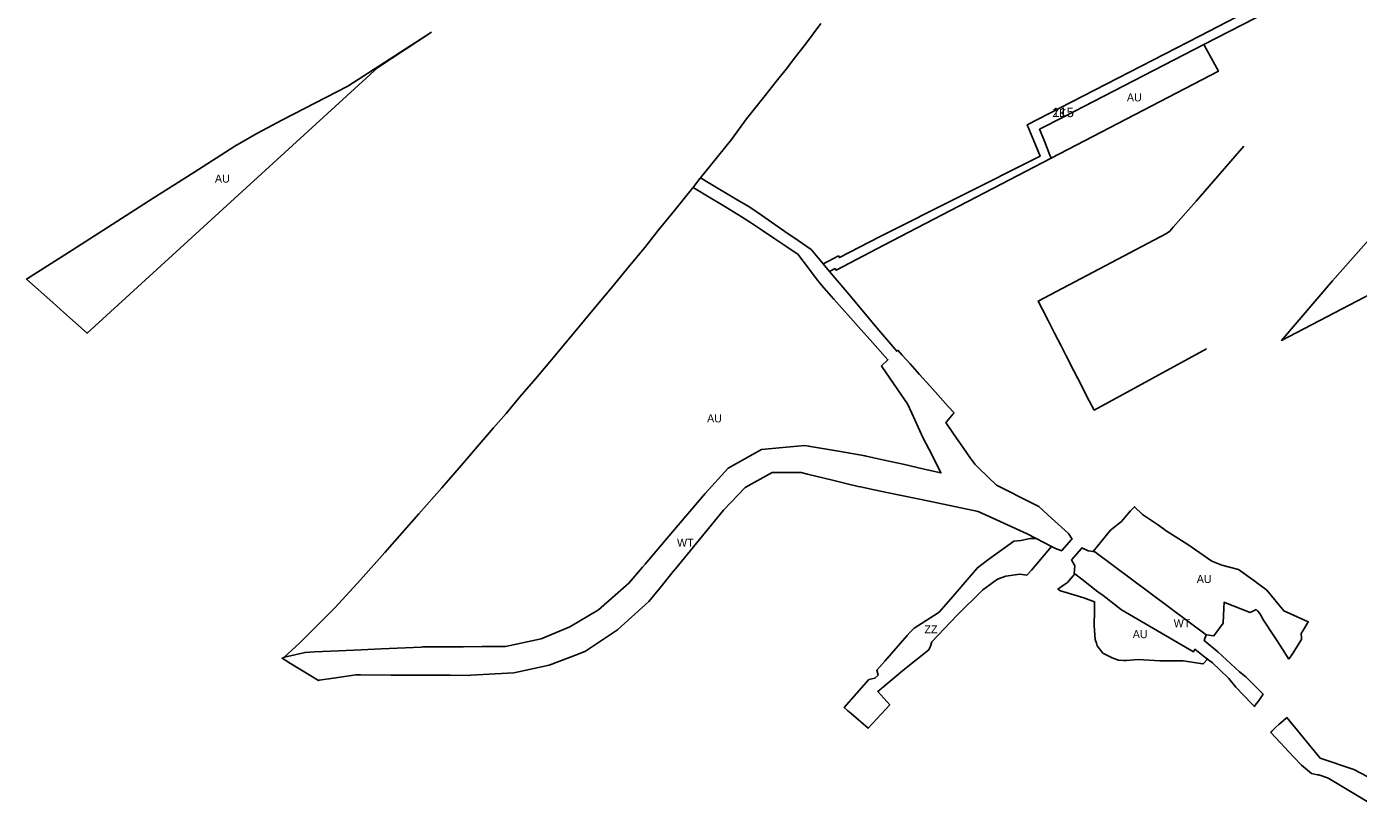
# Model space of a CAD drawing. Extents: x -537068 to -534056, y -1176840 to -1172401.
# Drawn here: x -536912 to -536080, y -1175434 to -1174949 of the extents above; entities that cross this region are included whole.
import ezdxf

# ---------------------------------------------------------------- set-up
doc = ezdxf.new("R2010")
doc.units = 0
for name, color, linetype in [('90640013', 7, 'Continuous'), ('90670013', 7, 'Continuous'), ('90710023', 7, 'Continuous'), ('90750013', 7, 'Continuous'), ('90910012', 7, 'Continuous'), ('ID_navrh', 7, 'Continuous')]:
    doc.layers.add(name, color=color, linetype=linetype)

msp = doc.modelspace()

# ---------------------------------------------------------------- linework, layer by layer
at = {"layer": '90640013'}
for points in [[(-536490.68, -1175043.69), (-536484.79, -1175047.2), (-536468.86, -1175056.7), (-536459.95, -1175062.02), (-536452.7, -1175067), (-536438, -1175077.11), (-536429.77, -1175082.77), (-536421.57, -1175088.4), (-536421.33, -1175088.69), (-536416.11, -1175094.9), (-536413.98, -1175097.44), (-536410.03, -1175102.14), (-536399.34, -1175114.87), (-536389.8, -1175126.23), (-536383.62, -1175133.58), (-536378.06, -1175140.2), (-536368.14, -1175152.02), (-536367.46, -1175151.36), (-536364.74, -1175154.39), (-536359.75, -1175159.95), (-536353.92, -1175166.46), (-536347.53, -1175173.58), (-536340.72, -1175181.18), (-536335.92, -1175186.53), (-536332.33, -1175190.53), (-536332.81, -1175191.09), (-536337.02, -1175196.03), (-536337.47, -1175196.56), (-536332.16, -1175204.17), (-536326.78, -1175211.87), (-536322.16, -1175218.49), (-536319.19, -1175222.74), (-536316.81, -1175225.04), (-536305.84, -1175235.63), (-536303.62, -1175236.76), (-536284.85, -1175246.29), (-536279.45, -1175249.03), (-536271.48, -1175256.23), (-536260.91, -1175265.77), (-536258.63, -1175269.32), (-536259.12, -1175269.87), (-536264.68, -1175276.25), (-536265.02, -1175276.59), (-536269.03, -1175275.21), (-536271.52, -1175273.92), (-536280.96, -1175269.04), (-536287.16, -1175265.83), (-536288.93, -1175264.91), (-536305.74, -1175257.27), (-536317.26, -1175252.03), (-536328.04, -1175249.78), (-536346.89, -1175245.84), (-536373.21, -1175240.34), (-536382.24, -1175238.45), (-536390.81, -1175236.66), (-536392.21, -1175236.37), (-536399.98, -1175234.5), (-536407.33, -1175232.74), (-536423.97, -1175228.74), (-536427.89, -1175227.8), (-536444.75, -1175227.76), (-536445.98, -1175227.76), (-536462.81, -1175237.16), (-536476.37, -1175251.23), (-536506.39, -1175287.87), (-536507.78, -1175289.57), (-536516.21, -1175299.87), (-536523.05, -1175308.22), (-536542.56, -1175325.99), (-536562.54, -1175339.42), (-536567.18, -1175341.2), (-536585.26, -1175348.14), (-536604.35, -1175352.21), (-536607.28, -1175352.83), (-536619.04, -1175353.49), (-536634.14, -1175354.33), (-536635.72, -1175354.42), (-536647.1, -1175354.38), (-536658.65, -1175354.34), (-536683.84, -1175354.25), (-536703.09, -1175354.18), (-536706.02, -1175354.17), (-536720.06, -1175356.19), (-536728.94, -1175357.47), (-536729.44, -1175357.63), (-536734.09, -1175354.78), (-536746.8, -1175346.98), (-536752.13, -1175343.71), (-536751.07, -1175343.25), (-536750.6, -1175343.05), (-536737.75, -1175340.09), (-536731.93, -1175339.82), (-536716.68, -1175339.12), (-536702.65, -1175338.47), (-536690.24, -1175337.9), (-536665, -1175336.74), (-536664.21, -1175336.7), (-536638.82, -1175336.52), (-536627.17, -1175336.44), (-536613.5, -1175336.34), (-536612.54, -1175336.33), (-536593.1, -1175332.31), (-536590.22, -1175331.72), (-536572.42, -1175324.22), (-536554.37, -1175313.52), (-536535.39, -1175296.91), (-536526.92, -1175286.9), (-536525.25, -1175284.92), (-536508.23, -1175264.81), (-536487.89, -1175240.78), (-536473.35, -1175225.12), (-536452.52, -1175213.27), (-536439.28, -1175212.07), (-536425.59, -1175210.82), (-536423.18, -1175211.23), (-536404.41, -1175214.45), (-536387.78, -1175217.31), (-536387.29, -1175217.42), (-536383.38, -1175218.3), (-536376.05, -1175219.95), (-536364.19, -1175222.62), (-536350.91, -1175225.62), (-536340.49, -1175227.97), (-536343.76, -1175221.53), (-536347.92, -1175213.35), (-536351.52, -1175206.27), (-536352.71, -1175203.93), (-536358.77, -1175190.72), (-536361.44, -1175184.9), (-536367.46, -1175176.11), (-536377.38, -1175161.61), (-536377.67, -1175161.19), (-536373.61, -1175157.28), (-536384.68, -1175144.91), (-536390.57, -1175138.32), (-536396.95, -1175131.19), (-536407.42, -1175119.5), (-536415.22, -1175110.79), (-536418.46, -1175106.49), (-536423.89, -1175099.29), (-536428.7, -1175092.92), (-536429.65, -1175091.66), (-536436.8, -1175086.86), (-536444.95, -1175081.39), (-536452.04, -1175076.63), (-536459.44, -1175071.66), (-536464.67, -1175068.15), (-536475.45, -1175061.63), (-536487.29, -1175054.48), (-536492.13, -1175051.55), (-536495.33, -1175049.61), (-536491.08, -1175044.18)], [(-536256.94, -1175290.98), (-536257.21, -1175290.77), (-536256.81, -1175285.98), (-536258.98, -1175282.35), (-536258.45, -1175281.76), (-536252.93, -1175275.41), (-536252.42, -1175274.85), (-536248.56, -1175276.64), (-536245.43, -1175277.08), (-536244.47, -1175277.22), (-536174.83, -1175329.11), (-536176.08, -1175332.67), (-536167.45, -1175339.65), (-536154.1, -1175352.24), (-536149.99, -1175355.36), (-536140.48, -1175364.96), (-536139.22, -1175366.23), (-536140.9, -1175368.58), (-536142.38, -1175370.67), (-536144.13, -1175373.13), (-536144.69, -1175373.91), (-536146.37, -1175372.18), (-536156.36, -1175361.85), (-536160.75, -1175356.36), (-536166.35, -1175351.05), (-536170.92, -1175346.71), (-536173.98, -1175344.3), (-536175.56, -1175343.05), (-536181.85, -1175338.08), (-536182.71, -1175339.67), (-536227.76, -1175313.5), (-536239.24, -1175304.64), (-536242.44, -1175302.17), (-536252.47, -1175294.43)]]:
    msp.add_lwpolyline(points, close=True, dxfattribs=at)
msp.add_lwpolyline([(-536073.22, -1175433.76), (-536098.1, -1175418.81), (-536099.12, -1175418.47), (-536104.49, -1175416.66), (-536105.23, -1175416.52), (-536109.05, -1175415.82), (-536115.36, -1175410.61), (-536120, -1175405.62), (-536134.45, -1175390.08), (-536133.72, -1175389.22), (-536131.61, -1175387.06), (-536129.31, -1175385), (-536128.14, -1175384), (-536124.76, -1175381.12), (-536124.4, -1175380.82), (-536103.64, -1175406.19), (-536082.54, -1175413.15), (-536073.75, -1175417.73)], dxfattribs=at)
at = {"layer": '90670013'}
for points in [[(-535985, -1175030.71), (-535987.73, -1175031.78), (-535991.38, -1175035.55), (-536000.38, -1175039.92), (-536000.46, -1175039.74), (-536004.78, -1175040.95), (-536010.29, -1175043.85), (-536011.85, -1175044.67), (-536033.55, -1175055.88), (-536033.44, -1175056.08), (-536024.99, -1175070.7), (-536022.89, -1175074.89), (-536016.75, -1175086.68), (-536061.58, -1175110.73), (-536127.83, -1175145.22), (-536095.85, -1175107.94), (-536063.63, -1175071.65), (-536056.68, -1175063.43), (-536036.63, -1175040.94), (-535995.32, -1175018.56)], [(-536280.96, -1175269.04), (-536271.52, -1175273.92), (-536284.03, -1175288.64), (-536286.76, -1175291.86), (-536291.26, -1175291.15), (-536299.98, -1175292.46), (-536305.13, -1175294.43), (-536314.41, -1175300.96), (-536330.65, -1175316.94), (-536346.17, -1175333.57), (-536347.12, -1175336.1), (-536348.02, -1175338.47), (-536363.36, -1175350.59), (-536379.99, -1175364.45), (-536372.45, -1175372.79), (-536385.98, -1175387.51), (-536396.65, -1175378.26), (-536398.63, -1175376.55), (-536400.91, -1175374.57), (-536385.53, -1175356.93), (-536381.74, -1175356.21), (-536379.74, -1175354.25), (-536380.6, -1175351.29), (-536375.6, -1175345.56), (-536361.65, -1175329.57), (-536359.99, -1175327.66), (-536357.28, -1175324.87), (-536345.13, -1175317.2), (-536341.62, -1175314.98), (-536334.39, -1175306.56), (-536317.76, -1175287.21), (-536311.39, -1175282.57), (-536294.87, -1175270.55), (-536290.53, -1175270.13), (-536284.76, -1175268.91)]]:
    msp.add_lwpolyline(points, close=True, dxfattribs=at)
at = {"layer": '90710023'}
msp.add_lwpolyline([(-536136.12, -1174939.73), (-536176.32, -1174960.44), (-536263.77, -1175005.5), (-536278.94, -1175013.32), (-536275.9, -1175020.87), (-536272.46, -1175029.43), (-536271.65, -1175031.44), (-536376.08, -1175085.82), (-536406.02, -1175101.41), (-536406.67, -1175100.37), (-536407.88, -1175101.01), (-536410.03, -1175102.14), (-536413.98, -1175097.44), (-536410.68, -1175095.7), (-536404.54, -1175092.46), (-536403.87, -1175093.53), (-536378.81, -1175080.48), (-536278.61, -1175030.21), (-536281.47, -1175023.11), (-536286.55, -1175010.49), (-536266.52, -1175000.17), (-536179.07, -1174955.11), (-536138.87, -1174934.4)], dxfattribs=at)
at = {"layer": '90750013'}
msp.add_lwpolyline([(-536138.87, -1174934.4), (-536179.07, -1174955.11), (-536266.52, -1175000.17), (-536286.55, -1175010.49), (-536281.47, -1175023.11), (-536278.61, -1175030.21), (-536378.81, -1175080.48), (-536403.87, -1175093.53), (-536404.54, -1175092.46), (-536410.68, -1175095.7), (-536413.98, -1175097.44), (-536416.11, -1175094.9), (-536421.33, -1175088.69), (-536421.57, -1175088.4), (-536429.77, -1175082.77), (-536438, -1175077.11), (-536452.7, -1175067), (-536459.95, -1175062.02), (-536468.86, -1175056.7), (-536484.79, -1175047.2), (-536490.68, -1175043.69), (-536484.52, -1175036.01), (-536471.26, -1175019.83), (-536461.87, -1175006.88), (-536450.22, -1174992.32), (-536443.42, -1174983.42), (-536437.27, -1174975.81), (-536431.45, -1174968.05), (-536425.14, -1174960.28), (-536415.59, -1174947.33)], dxfattribs=at)
for points in [[(-536658.72, -1174952.6), (-536692.18, -1174974.82), (-536873.93, -1175140.73), (-536881.21, -1175134.2), (-536888.47, -1175127.69), (-536895.32, -1175121.59), (-536911.66, -1175106.88), (-536883.25, -1175088.77), (-536858.18, -1175072.79), (-536832.53, -1175056.44), (-536807.15, -1175040.26), (-536781.54, -1175023.94), (-536767.9, -1175016.02), (-536751.83, -1175007.36), (-536711.11, -1174986.49)], [(-536176.32, -1174960.44), (-536167.15, -1174977.02), (-536271.65, -1175031.44), (-536272.46, -1175029.43), (-536275.9, -1175020.87), (-536278.94, -1175013.32), (-536263.77, -1175005.5)], [(-536751.07, -1175343.25), (-536741.24, -1175334.42), (-536718.93, -1175312.13), (-536703.1, -1175294.68), (-536687.97, -1175277.68), (-536666.61, -1175253.57), (-536652.37, -1175237.23), (-536638.82, -1175221.78), (-536633.72, -1175215.87), (-536630.12, -1175211.7), (-536619.97, -1175199.77), (-536612.2, -1175190.87), (-536603.3, -1175180.35), (-536593.75, -1175169.19), (-536584.77, -1175158.59), (-536578.54, -1175151.06), (-536563.09, -1175132.53), (-536555, -1175122.74), (-536546.34, -1175112.47), (-536536.95, -1175100.98), (-536524.65, -1175086.09), (-536517.37, -1175076.71), (-536507.02, -1175064.09), (-536495.77, -1175050.17), (-536495.34, -1175049.61), (-536495.33, -1175049.61), (-536492.13, -1175051.55), (-536487.29, -1175054.48), (-536475.45, -1175061.63), (-536464.67, -1175068.15), (-536459.44, -1175071.66), (-536452.04, -1175076.63), (-536444.95, -1175081.39), (-536436.8, -1175086.86), (-536429.65, -1175091.66), (-536428.7, -1175092.92), (-536423.89, -1175099.29), (-536418.46, -1175106.49), (-536415.22, -1175110.79), (-536407.42, -1175119.5), (-536396.95, -1175131.19), (-536390.57, -1175138.32), (-536384.68, -1175144.91), (-536373.61, -1175157.28), (-536377.67, -1175161.19), (-536377.38, -1175161.61), (-536367.46, -1175176.11), (-536361.44, -1175184.9), (-536358.77, -1175190.72), (-536352.71, -1175203.93), (-536351.52, -1175206.27), (-536347.92, -1175213.35), (-536343.76, -1175221.53), (-536340.49, -1175227.97), (-536350.91, -1175225.62), (-536364.19, -1175222.62), (-536376.05, -1175219.95), (-536383.38, -1175218.3), (-536387.29, -1175217.42), (-536387.78, -1175217.31), (-536404.41, -1175214.45), (-536423.18, -1175211.23), (-536425.59, -1175210.82), (-536439.28, -1175212.07), (-536452.52, -1175213.27), (-536473.35, -1175225.12), (-536487.89, -1175240.78), (-536508.23, -1175264.81), (-536525.25, -1175284.92), (-536526.92, -1175286.9), (-536535.39, -1175296.91), (-536554.37, -1175313.52), (-536572.42, -1175324.22), (-536590.22, -1175331.72), (-536593.1, -1175332.31), (-536612.54, -1175336.33), (-536613.5, -1175336.34), (-536627.17, -1175336.44), (-536638.82, -1175336.52), (-536664.21, -1175336.7), (-536665, -1175336.74), (-536690.24, -1175337.9), (-536702.65, -1175338.47), (-536716.68, -1175339.12), (-536731.93, -1175339.82), (-536737.75, -1175340.09), (-536750.6, -1175343.05)], [(-536123.14, -1175344.33), (-536128.61, -1175335.86), (-536130.52, -1175332.91), (-536132.93, -1175329.17), (-536138.92, -1175319.89), (-536141.24, -1175315.79), (-536142.73, -1175314.22), (-536143.56, -1175313.35), (-536147.33, -1175315.23), (-536162.7, -1175309.09), (-536163.62, -1175308.72), (-536163.77, -1175312.48), (-536164.16, -1175321.85), (-536169.96, -1175329.82), (-536174.83, -1175329.11), (-536244.47, -1175277.22), (-536245.43, -1175277.08), (-536234.54, -1175263.73), (-536227.77, -1175258.32), (-536225.62, -1175255.88), (-536221.99, -1175251.75), (-536221, -1175250.62), (-536219.68, -1175249.12), (-536214.58, -1175253.88), (-536205.32, -1175260.27), (-536199.13, -1175264.55), (-536195.9, -1175266.57), (-536186.22, -1175272.68), (-536171.39, -1175283.12), (-536165.09, -1175285.55), (-536154.59, -1175288.29), (-536145.13, -1175295.25), (-536136.94, -1175301.28), (-536126.39, -1175314.2), (-536113.86, -1175319.75), (-536111.06, -1175320.99), (-536113.39, -1175324.91), (-536115.4, -1175328.29), (-536115.24, -1175330.93), (-536115.18, -1175331.96), (-536120.96, -1175340.95)], [(-536256.94, -1175290.98), (-536252.47, -1175294.43), (-536242.44, -1175302.17), (-536239.24, -1175304.64), (-536227.76, -1175313.5), (-536182.71, -1175339.67), (-536181.85, -1175338.08), (-536175.56, -1175343.05), (-536173.98, -1175344.3), (-536176.77, -1175347.23), (-536176.99, -1175347.19), (-536189.18, -1175345.37), (-536203.82, -1175345.44), (-536217.31, -1175344.47), (-536224.52, -1175345.12), (-536225.56, -1175345.21), (-536226.51, -1175345.16), (-536229.59, -1175344.99), (-536230.18, -1175344.78), (-536233.5, -1175343.56), (-536239.33, -1175340.58), (-536242.85, -1175335.97), (-536243.38, -1175334.41), (-536244.16, -1175332.1), (-536244.69, -1175323.41), (-536244.55, -1175313.7), (-536244.48, -1175308.41), (-536251.19, -1175305.97), (-536265.73, -1175301.59), (-536267.4, -1175300.62), (-536262.6, -1175297.2), (-536261.38, -1175296.33)]]:
    msp.add_lwpolyline(points, close=True, dxfattribs=at)
at = {"layer": '90910012'}
msp.add_lwpolyline([(-536174.55, -1175150.52), (-536244.7, -1175188.78), (-536247.95, -1175182.88), (-536249.28, -1175180.28), (-536252.55, -1175173.87), (-536257.52, -1175164.12), (-536262.3, -1175154.77), (-536265.39, -1175148.71), (-536269.53, -1175140.6), (-536273.53, -1175132.76), (-536277, -1175125.95), (-536279.71, -1175120.65), (-536199.54, -1175078.53), (-536197.48, -1175076.92), (-536195.41, -1175074.54), (-536181.15, -1175058.17), (-536151.28, -1175023.87)], dxfattribs=at)

# ---------------------------------------------------------------- texts
at = {"layer": '90640013'}
for p in [(-536505.38, -1175274.04), (-536195.1, -1175324.38)]:
    msp.add_text('WT', height=5, rotation=0, dxfattribs=at).set_placement(p)
at = {"layer": '90670013'}
msp.add_text('ZZ', height=5, rotation=360, dxfattribs=at).set_placement((-536350.82, -1175328.21))
at = {"layer": '90710023'}
msp.add_text('ZK', height=5, rotation=0, dxfattribs=at).set_placement((-536270.85, -1175005.78))
at = {"layer": '90750013'}
for rotation, p in [(360, (-536224.35, -1174995.94)), (360, (-536794.04, -1175046.67)), (0, (-536486.6, -1175196.43)), (360, (-536180.71, -1175296.72)), (360, (-536220.69, -1175331.19))]:
    msp.add_text('AU', height=5, rotation=rotation, dxfattribs=at).set_placement(p)
at = {"layer": 'ID_navrh'}
msp.add_text('115', height=6, rotation=360, dxfattribs=at).set_placement((-536270.85, -1175005.78))

doc.saveas('drawing.dxf')
